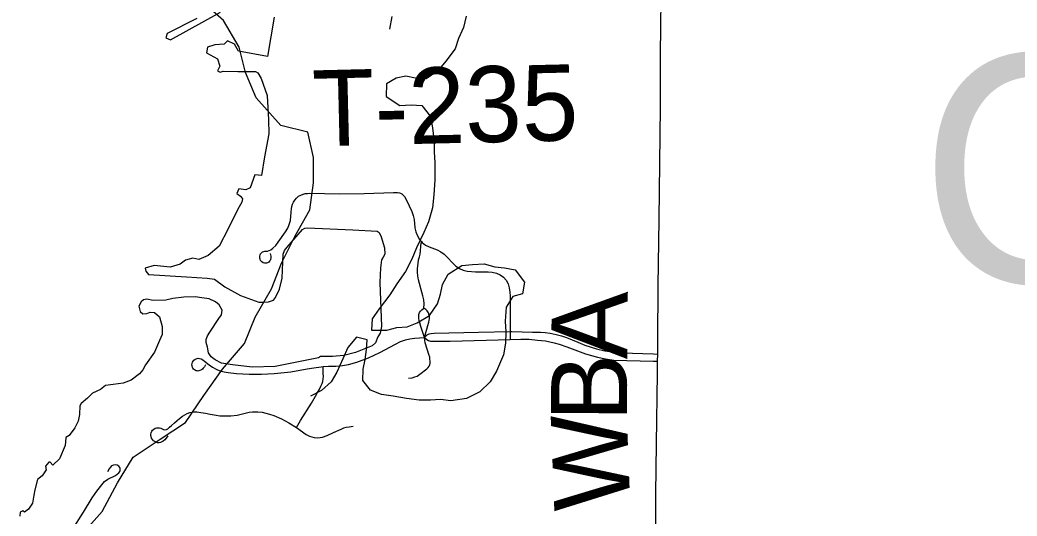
# Model space of a CAD drawing. Extents: x 0 to 34, y 0 to 22.
# Drawn here: x 5.8393 to 6.2117, y 19.8487 to 20.0341 of the extents above; entities that cross this region are included whole.
import ezdxf

# ---------------------------------------------------------------- set-up
doc = ezdxf.new("R2010")
doc.units = 0
for name, color, linetype in [('GM_X_Corporation', 7, 'Continuous'), ('GM_X_County_Road', 7, 'Continuous'), ('GM_X_County_Road_Text', 7, 'Continuous'), ('GM_X_Major_Lake', 7, 'Continuous'), ('GM_X_Minor_River', 7, 'Continuous'), ('GM_X_Township_Road', 7, 'Continuous'), ('GM_X_Township_Road_Text', 7, 'Continuous'), ('GM_X_Township_Text', 7, 'Continuous')]:
    doc.layers.add(name, color=color, linetype=linetype)

msp = doc.modelspace()

# ---------------------------------------------------------------- linework, layer by layer
at = {"layer": 'GM_X_Corporation'}
for points in [[(5.90542, 20.0346), (5.89438, 20.02901), (5.89385, 20.02741), (5.89558, 20.02662), (5.9142, 20.03699)], [(5.90542, 20.0346), (5.89438, 20.02901), (5.89385, 20.02741), (5.89558, 20.02662), (5.9142, 20.03699)], [(5.93428, 20.03513), (5.93176, 20.02037), (5.92092, 20.02243), (5.91952, 20.02502), (5.91689, 20.02624), (5.91566, 20.02502), (5.91214, 20.02476), (5.90941, 20.02396), (5.90901, 20.02183), (5.91307, 20.01957), (5.914, 20.01677), (5.91306, 20.01512), (5.91409, 20.01453), (5.91527, 20.01497), (5.92068, 20.01488), (5.92733, 20.01484), (5.92824, 20.01436), (5.92945, 20.01219), (5.93163, 20.00585), (5.93219, 19.99673), (5.93228, 19.99151), (5.93067, 19.98287), (5.92954, 19.97596), (5.92711, 19.97622), (5.92533, 19.97139), (5.92376, 19.97061), (5.92107, 19.97096), (5.9203, 19.96921), (5.92176, 19.96818), (5.92246, 19.96718), (5.9222, 19.96601), (5.92068, 19.96331), (5.91714, 19.95601), (5.91373, 19.94958), (5.90969, 19.94606), (5.90612, 19.94455), (5.90387, 19.94502), (5.90122, 19.94428), (5.89921, 19.94281), (5.89539, 19.94168), (5.88953, 19.94228), (5.88609, 19.94133), (5.88636, 19.94016), (5.88736, 19.9389), (5.9016, 19.93807), (5.90921, 19.93755), (5.91195, 19.93724), (5.91586, 19.93433), (5.92168, 19.93112), (5.92854, 19.9286), (5.93032, 19.92855), (5.93215, 19.92877), (5.93402, 19.92938), (5.9348, 19.93034), (5.93632, 19.93347), (5.93727, 19.93764), (5.93767, 19.94659), (5.93814, 19.94789), (5.93919, 19.94911), (5.94488, 19.95571), (5.9457, 19.95623), (5.94657, 19.95636), (5.96369, 19.95567), (5.97269, 19.9551), (5.97351, 19.95462), (5.9742, 19.95297), (5.97551, 19.94893), (5.97555, 19.94659), (5.97499, 19.94546), (5.97434, 19.94446), (5.97399, 19.94142), (5.97368, 19.93599), (5.97442, 19.91956), (5.9739, 19.91704), (5.97295, 19.9157), (5.97212, 19.91344), (5.97082, 19.91235), (5.96469, 19.90983), (5.96035, 19.90866), (5.95605, 19.90831), (5.95161, 19.90831), (5.95079, 19.90779), (5.93462, 19.90462), (5.92602, 19.90431), (5.91872, 19.90523), (5.91464, 19.90583), (5.91221, 19.90705), (5.91077, 19.90818), (5.90973, 19.90966), (5.90934, 19.91178), (5.90895, 19.91357), (5.90895, 19.91461), (5.90934, 19.916), (5.91021, 19.91739), (5.91364, 19.92247), (5.91464, 19.92391), (5.91481, 19.9256), (5.91373, 19.92764), (5.91238, 19.92873), (5.90999, 19.92986), (5.90725, 19.93021), (5.90473, 19.9306), (5.90056, 19.93042), (5.89648, 19.92995), (5.89387, 19.92938), (5.88914, 19.92929), (5.88679, 19.92973), (5.88553, 19.92951), (5.88458, 19.92873), (5.88371, 19.92708), (5.88418, 19.92512), (5.88522, 19.9243), (5.88675, 19.92434), (5.88801, 19.92491), (5.88961, 19.92469), (5.89144, 19.92317), (5.89248, 19.91956), (5.89244, 19.91657), (5.89148, 19.91426), (5.88961, 19.90987), (5.88623, 19.90522), (5.88527, 19.90327), (5.88397, 19.90179), (5.88084, 19.8994), (5.87793, 19.8984), (5.8741, 19.89788), (5.87128, 19.89741), (5.86941, 19.89597), (5.8665, 19.89458), (5.86455, 19.89271), (5.86216, 19.8908), (5.86176, 19.88989), (5.86163, 19.88667), (5.86103, 19.88419), (5.85981, 19.88163), (5.85777, 19.87872), (5.85646, 19.87798), (5.85638, 19.87646), (5.8562, 19.87507), (5.85412, 19.87003), (5.85164, 19.86764), (5.85069, 19.86877), (5.85008, 19.86886), (5.84886, 19.8673), (5.84916, 19.8659), (5.8476, 19.86373), (5.84586, 19.86234), (5.84491, 19.85843), (5.84456, 19.85652), (5.84404, 19.85344), (5.84256, 19.85126), (5.841, 19.85018), (5.84039, 19.85061), (5.83939, 19.85013), (5.83935, 19.84857)], [(5.93428, 20.03513), (5.93176, 20.02037), (5.92092, 20.02243), (5.91952, 20.02502), (5.91689, 20.02624), (5.91566, 20.02502), (5.91214, 20.02476), (5.90941, 20.02396), (5.90901, 20.02183), (5.91307, 20.01957), (5.914, 20.01677), (5.91306, 20.01512), (5.91409, 20.01453), (5.91527, 20.01497), (5.92068, 20.01488), (5.92733, 20.01484), (5.92824, 20.01436), (5.92945, 20.01219), (5.93163, 20.00585), (5.93219, 19.99673), (5.93228, 19.99151), (5.93067, 19.98287), (5.92954, 19.97596), (5.92711, 19.97622), (5.92533, 19.97139), (5.92376, 19.97061), (5.92107, 19.97096), (5.9203, 19.96921), (5.92176, 19.96818), (5.92246, 19.96718), (5.9222, 19.96601), (5.92068, 19.96331), (5.91714, 19.95601), (5.91373, 19.94958), (5.90969, 19.94606), (5.90612, 19.94455), (5.90387, 19.94502), (5.90122, 19.94428), (5.89921, 19.94281), (5.89539, 19.94168), (5.88953, 19.94228), (5.88609, 19.94133), (5.88636, 19.94016), (5.88736, 19.9389), (5.9016, 19.93807), (5.90921, 19.93755), (5.91195, 19.93724), (5.91586, 19.93433), (5.92168, 19.93112), (5.92854, 19.9286), (5.93032, 19.92855), (5.93215, 19.92877), (5.93402, 19.92938), (5.9348, 19.93034), (5.93632, 19.93347), (5.93727, 19.93764), (5.93767, 19.94659), (5.93814, 19.94789), (5.93919, 19.94911), (5.94488, 19.95571), (5.9457, 19.95623), (5.94657, 19.95636), (5.96369, 19.95567), (5.97269, 19.9551), (5.97351, 19.95462), (5.9742, 19.95297), (5.97551, 19.94893), (5.97555, 19.94659), (5.97499, 19.94546), (5.97434, 19.94446), (5.97399, 19.94142), (5.97368, 19.93599), (5.97442, 19.91956), (5.9739, 19.91704), (5.97295, 19.9157), (5.97212, 19.91344), (5.97082, 19.91235), (5.96469, 19.90983), (5.96035, 19.90866), (5.95605, 19.90831), (5.95161, 19.90831), (5.95079, 19.90779), (5.93462, 19.90462), (5.92602, 19.90431), (5.91872, 19.90523), (5.91464, 19.90583), (5.91221, 19.90705), (5.91077, 19.90818), (5.90973, 19.90966), (5.90934, 19.91178), (5.90895, 19.91357), (5.90895, 19.91461), (5.90934, 19.916), (5.91021, 19.91739), (5.91364, 19.92247), (5.91464, 19.92391), (5.91481, 19.9256), (5.91373, 19.92764), (5.91238, 19.92873), (5.90999, 19.92986), (5.90725, 19.93021), (5.90473, 19.9306), (5.90056, 19.93042), (5.89648, 19.92995), (5.89387, 19.92938), (5.88914, 19.92929), (5.88679, 19.92973), (5.88553, 19.92951), (5.88458, 19.92873), (5.88371, 19.92708), (5.88418, 19.92512), (5.88522, 19.9243), (5.88675, 19.92434), (5.88801, 19.92491), (5.88961, 19.92469), (5.89144, 19.92317), (5.89248, 19.91956), (5.89244, 19.91657), (5.89148, 19.91426), (5.88961, 19.90987), (5.88623, 19.90522), (5.88527, 19.90327), (5.88397, 19.90179), (5.88084, 19.8994), (5.87793, 19.8984), (5.8741, 19.89788), (5.87128, 19.89741), (5.86941, 19.89597), (5.8665, 19.89458), (5.86455, 19.89271), (5.86216, 19.8908), (5.86176, 19.88989), (5.86163, 19.88667), (5.86103, 19.88419), (5.85981, 19.88163), (5.85777, 19.87872), (5.85646, 19.87798), (5.85638, 19.87646), (5.8562, 19.87507), (5.85412, 19.87003), (5.85164, 19.86764), (5.85069, 19.86877), (5.85008, 19.86886), (5.84886, 19.8673), (5.84916, 19.8659), (5.8476, 19.86373), (5.84586, 19.86234), (5.84491, 19.85843), (5.84456, 19.85652), (5.84404, 19.85344), (5.84256, 19.85126), (5.841, 19.85018), (5.84039, 19.85061), (5.83939, 19.85013), (5.83935, 19.84857)]]:
    msp.add_lwpolyline(points, dxfattribs=at)
at = {"layer": 'GM_X_County_Road'}
for points in [[(6.07746, 19.90651), (6.07751, 19.90922), (6.07761, 19.91447), (6.07765, 19.93467), (6.07802, 19.95953), (6.07849, 20.00148), (6.07856, 20.01856), (6.07873, 20.0341), (6.07876, 20.03932)], [(6.07684, 19.84572), (6.07681, 19.85702), (6.07711, 19.87566), (6.07738, 19.90208), (6.07746, 19.90651)]]:
    msp.add_lwpolyline(points, dxfattribs=at)
at = {"layer": 'GM_X_Major_Lake'}
for points in [[(5.87007, 19.85039), (5.87576, 19.86104), (5.88164, 19.87073), (5.89169, 19.87739), (5.90118, 19.88366), (5.90801, 19.89373), (5.91502, 19.90362), (5.92318, 19.91312), (5.92716, 19.92301), (5.93323, 19.93365), (5.93702, 19.94316), (5.94214, 19.95342), (5.94764, 19.96311), (5.94897, 19.97319), (5.94897, 19.98269), (5.94688, 19.99219), (5.93682, 19.99466), (5.92752, 20.00493), (5.92353, 20.01443), (5.92125, 20.02393), (5.91537, 20.03382), (5.90512, 20.04294)], [(5.86115, 19.84032), (5.87007, 19.85039)]]:
    msp.add_lwpolyline(points, dxfattribs=at)
at = {"layer": 'GM_X_Minor_River'}
for points in [[(6.00593, 20.03549), (6.005, 20.0313), (6.00313, 20.02711), (6.00182, 20.0233), (5.99843, 20.01872), (5.99541, 20.01509), (5.99106, 20.01203), (5.98707, 20.01239), (5.98346, 20.01313), (5.97986, 20.01235), (5.97626, 20.01025), (5.97609, 20.00549), (5.98124, 20.00209), (5.98541, 20.0023), (5.9894, 20.00213), (5.99265, 19.99796), (5.99343, 19.99378), (5.99403, 19.98846), (5.99405, 19.98484), (5.99426, 19.98066), (5.99429, 19.97439), (5.99394, 19.96868), (5.9934, 19.96392), (5.99191, 19.95859), (5.99022, 19.95459), (5.9874, 19.94887), (5.98572, 19.94468), (5.98327, 19.9401), (5.98007, 19.93552), (5.97743, 19.93132), (5.97347, 19.92617), (5.97084, 19.92236), (5.97067, 19.91817), (5.97636, 19.9182), (5.98015, 19.91917), (5.98395, 19.91937), (5.98774, 19.92091), (5.99228, 19.9236), (5.9953, 19.92798), (5.99641, 19.9316), (5.99716, 19.93522), (5.99922, 19.93903), (6.00433, 19.94229), (6.00832, 19.94269), (6.01268, 19.9429), (6.01667, 19.94178), (6.02028, 19.94142), (6.02427, 19.94067), (6.02772, 19.93612), (6.02698, 19.93175), (6.02338, 19.93078), (6.02093, 19.92677), (6.02058, 19.92145), (6.02079, 19.91746), (6.02062, 19.91327), (6.01988, 19.90889), (6.01726, 19.90279), (6.015, 19.89879), (6.01103, 19.89516), (6.00611, 19.89266), (6.00023, 19.89168), (5.99643, 19.89224), (5.99264, 19.89203), (5.98846, 19.89201), (5.98371, 19.89256), (5.97877, 19.89349), (5.9744, 19.89404), (5.97022, 19.89573), (5.96735, 19.89933), (5.96752, 19.90351), (5.96826, 19.90713), (5.96881, 19.91093), (5.96898, 19.91455), (5.96499, 19.91548), (5.96178, 19.91166), (5.9599, 19.90747), (5.95765, 19.90251), (5.95558, 19.89889), (5.95199, 19.89564), (5.94783, 19.89353)], [(5.97748, 20.0306), (5.9784, 20.03536)]]:
    msp.add_lwpolyline(points, dxfattribs=at)
at = {"layer": 'GM_X_Township_Road'}
for points in [[(5.93279, 19.9468), (5.93299, 19.94575), (5.93303, 19.94513), (5.93296, 19.94451), (5.93283, 19.94419), (5.9326, 19.94388), (5.93235, 19.94362), (5.93208, 19.94345), (5.93173, 19.9433), (5.93136, 19.94321), (5.931, 19.94317), (5.93062, 19.94321), (5.93021, 19.94333), (5.92968, 19.94365), (5.92943, 19.9439), (5.92922, 19.94422), (5.92907, 19.94463), (5.92898, 19.945), (5.92895, 19.94537), (5.92894, 19.9458), (5.92904, 19.94628), (5.92921, 19.94664), (5.92953, 19.94708), (5.92992, 19.94738), (5.93041, 19.94756), (5.93081, 19.94762), (5.93139, 19.94766), (5.93183, 19.94773), (5.93241, 19.94794), (5.933, 19.94823), (5.93377, 19.94878), (5.93486, 19.94985), (5.93583, 19.95107), (5.93857, 19.95489), (5.93935, 19.95623), (5.93994, 19.95767), (5.94032, 19.95918), (5.94065, 19.9623), (5.94077, 19.96355), (5.94089, 19.96435), (5.94114, 19.96519), (5.94155, 19.96602), (5.942, 19.96673), (5.94267, 19.96753), (5.94339, 19.96817), (5.94428, 19.96866), (5.94506, 19.96899), (5.94586, 19.9692), (5.94668, 19.96928), (5.94757, 19.96932), (5.95851, 19.96905), (5.96788, 19.96919), (5.97884, 19.9696), (5.98035, 19.96958), (5.98107, 19.9695), (5.98143, 19.96939), (5.98191, 19.96913), (5.98238, 19.96873), (5.9829, 19.96811), (5.98366, 19.96673), (5.98563, 19.96244), (5.98619, 19.96099), (5.98654, 19.95948), (5.98686, 19.95637), (5.98719, 19.95486), (5.98776, 19.95341), (5.98857, 19.95207), (5.98924, 19.95128)], [(5.99018, 19.92642), (5.99027, 19.92796), (5.99012, 19.92948), (5.98984, 19.93099), (5.98815, 19.93694), (5.98791, 19.93847), (5.98784, 19.93973), (5.98784, 19.94116), (5.98803, 19.94311), (5.98823, 19.94438), (5.98859, 19.94557), (5.98879, 19.94649), (5.98895, 19.94768), (5.98906, 19.94967), (5.98924, 19.95128)], [(5.98924, 19.95128), (5.98958, 19.95088), (5.99078, 19.94993), (5.99218, 19.94924), (5.99512, 19.94818), (5.99649, 19.94747), (5.99773, 19.94654), (5.99886, 19.94545), (6.00099, 19.94315), (6.00215, 19.94211), (6.00344, 19.94125), (6.00485, 19.94063), (6.00635, 19.94024), (6.00791, 19.94004), (6.00947, 19.93996), (6.01418, 19.93993), (6.01574, 19.93979), (6.01725, 19.93945), (6.01868, 19.93884), (6.01994, 19.93794), (6.02095, 19.93679), (6.02167, 19.93542), (6.02208, 19.93393), (6.0223, 19.93237), (6.02238, 19.9308), (6.02243, 19.91764)], [(5.99048, 19.91542), (5.98906, 19.91957), (5.98863, 19.92085), (5.98844, 19.92179), (5.98833, 19.92256), (5.9883, 19.92332), (5.98833, 19.92405), (5.98851, 19.92472), (5.98888, 19.92529), (5.98939, 19.9258), (5.99018, 19.92642)], [(5.99048, 19.91542), (5.99128, 19.91855), (5.99168, 19.91987), (5.99205, 19.92117), (5.99219, 19.92187), (5.99227, 19.92241), (5.99228, 19.92284), (5.99212, 19.9238), (5.99187, 19.92463), (5.99146, 19.92532), (5.99092, 19.92591), (5.99018, 19.92642)], [(5.99048, 19.91542), (5.99139, 19.91641), (5.99212, 19.91681), (5.99292, 19.91695), (5.99398, 19.91705), (6.01057, 19.91746), (6.02243, 19.91764)], [(6.02243, 19.91764), (6.023, 19.91766), (6.03077, 19.91745), (6.03372, 19.91736), (6.03544, 19.91725), (6.0374, 19.917), (6.03955, 19.91652), (6.04152, 19.91598), (6.04341, 19.9154), (6.04767, 19.91365), (6.05026, 19.9126), (6.0547, 19.91117), (6.05771, 19.91043), (6.06088, 19.91001), (6.06408, 19.90973), (6.07592, 19.90928), (6.07751, 19.90922)], [(6.02243, 19.91764), (6.02244, 19.9155), (6.02245, 19.91469)], [(5.95254, 19.90452), (5.9546, 19.90466), (5.95736, 19.90474), (5.95974, 19.90497), (5.9621, 19.90537), (5.9651, 19.90621), (5.96949, 19.90784), (5.97375, 19.90978), (5.97963, 19.91291), (5.98146, 19.91385), (5.98329, 19.91453), (5.98491, 19.91495), (5.98663, 19.91521), (5.99048, 19.91542)], [(5.98449, 19.90019), (5.98577, 19.90037), (5.98684, 19.90066), (5.98763, 19.90098), (5.98873, 19.90168), (5.99124, 19.90373), (5.99177, 19.90424), (5.99215, 19.90474), (5.99235, 19.90523), (5.99252, 19.90581), (5.99255, 19.90651), (5.99247, 19.90736), (5.99235, 19.90806), (5.99209, 19.90908), (5.99159, 19.91062), (5.99113, 19.91184), (5.99086, 19.91263), (5.99069, 19.91339), (5.99048, 19.91542)], [(5.99048, 19.91542), (5.99128, 19.9147), (5.9919, 19.91426), (5.9926, 19.91406), (6, 19.91406), (6.02245, 19.91469)], [(6.02245, 19.91469), (6.02645, 19.9148), (6.02956, 19.91475), (6.03265, 19.91447), (6.03562, 19.91412), (6.03879, 19.91347), (6.04075, 19.91292), (6.04359, 19.91186), (6.05056, 19.90931), (6.05503, 19.908), (6.05807, 19.90737), (6.06116, 19.90698), (6.07581, 19.90655), (6.07746, 19.90651)], [(5.9086, 19.90518), (5.90842, 19.90474), (5.90823, 19.90441), (5.9078, 19.9039), (5.90748, 19.90356), (5.9071, 19.9033), (5.90657, 19.90302), (5.90621, 19.90292), (5.90589, 19.90288), (5.90558, 19.9029), (5.90516, 19.90298), (5.90485, 19.90309), (5.90422, 19.90354), (5.90395, 19.90389), (5.90375, 19.90423), (5.9036, 19.90479), (5.90358, 19.90524), (5.90363, 19.90572), (5.90382, 19.90621), (5.90401, 19.90655), (5.90425, 19.90688), (5.90463, 19.90723), (5.90512, 19.90749), (5.90553, 19.9076), (5.90595, 19.90765), (5.90643, 19.90761), (5.90703, 19.90742), (5.90759, 19.90706), (5.90821, 19.90655), (5.90995, 19.90516), (5.91127, 19.90432), (5.91266, 19.90362), (5.91404, 19.90298), (5.91561, 19.90262), (5.91715, 19.90237), (5.92024, 19.90193), (5.92491, 19.90164), (5.92959, 19.90167), (5.93426, 19.90193), (5.94046, 19.90263), (5.94663, 19.90372), (5.94912, 19.90413), (5.95184, 19.90447), (5.95254, 19.90452)], [(5.94258, 19.88174), (5.94417, 19.88435), (5.94817, 19.89091), (5.94975, 19.89354), (5.95052, 19.89487), (5.95105, 19.89582), (5.95173, 19.89718), (5.95215, 19.8982), (5.95241, 19.89899), (5.95264, 19.89998), (5.95268, 19.90092), (5.95264, 19.90182), (5.95254, 19.90452)], [(5.89455, 19.87864), (5.89393, 19.87772), (5.89345, 19.87718), (5.89281, 19.87664), (5.89233, 19.87635), (5.89179, 19.87616), (5.89133, 19.87609), (5.89073, 19.87609), (5.89023, 19.87624), (5.88969, 19.87649), (5.88922, 19.87683), (5.88883, 19.8773), (5.88853, 19.8778), (5.88833, 19.87838), (5.88824, 19.87879), (5.88824, 19.87927), (5.88834, 19.8798), (5.88856, 19.88035), (5.88884, 19.88073), (5.88931, 19.88116), (5.88989, 19.88146), (5.89038, 19.88161), (5.89091, 19.8817), (5.8914, 19.88166), (5.89196, 19.8815), (5.89241, 19.88128), (5.89296, 19.88101), (5.89335, 19.88094), (5.89405, 19.88105), (5.89459, 19.88133), (5.89517, 19.88185), (5.89592, 19.88246), (5.8971, 19.88353), (5.89801, 19.88433), (5.89895, 19.88516), (5.90009, 19.88599), (5.90092, 19.88652), (5.90182, 19.88701), (5.90284, 19.88735), (5.90352, 19.88754), (5.90435, 19.88761), (5.90541, 19.88761), (5.90685, 19.88742), (5.90862, 19.88709), (5.9104, 19.88678), (5.91263, 19.88633), (5.91403, 19.88618), (5.91576, 19.8861), (5.91807, 19.88614), (5.92042, 19.88643), (5.92498, 19.88747), (5.92616, 19.88758), (5.92714, 19.88762), (5.92816, 19.88762), (5.92974, 19.88747), (5.93114, 19.88713), (5.93258, 19.88675), (5.9342, 19.88622), (5.93704, 19.88497), (5.9397, 19.88355), (5.94258, 19.88174)], [(5.94258, 19.88174), (5.94621, 19.8792), (5.9475, 19.87859), (5.94837, 19.87825), (5.94924, 19.87807), (5.95041, 19.87795), (5.95143, 19.87806), (5.95238, 19.87821), (5.95404, 19.87874), (5.95643, 19.87987), (5.95927, 19.88119), (5.96027, 19.88161), (5.96118, 19.88192), (5.96227, 19.88208), (5.96382, 19.88229)], [(5.85899, 19.84362), (5.86309, 19.85018), (5.86631, 19.85547), (5.86806, 19.85801), (5.86997, 19.8604), (5.87098, 19.86154), (5.87216, 19.86247), (5.875, 19.86382), (5.87565, 19.86431), (5.87623, 19.86479), (5.87662, 19.86538), (5.87676, 19.86574), (5.87681, 19.86606), (5.87674, 19.86643), (5.8766, 19.86678), (5.87626, 19.86731), (5.87567, 19.86772), (5.87507, 19.86787), (5.87424, 19.8677), (5.87352, 19.86739), (5.87298, 19.86688), (5.87263, 19.86637), (5.872, 19.86523)]]:
    msp.add_lwpolyline(points, dxfattribs=at)

# ---------------------------------------------------------------- texts
at = {"layer": 'GM_X_County_Road_Text'}
for s, rotation, p in [('A', 89.5337, (6.06615, 19.90727)), ('B', 89.7346, (6.06604, 19.88396)), ('W', 92.2125, (6.06731, 19.85139))]:
    msp.add_text(s, height=0.02841, rotation=rotation, dxfattribs=at).set_placement(p)
at = {"layer": 'GM_X_Township_Road_Text'}
msp.add_text('T-235', height=0.028409, rotation=1.3766, dxfattribs=at).set_placement((5.94889, 19.98681))
at = {"layer": 'GM_X_Township_Text'}
msp.add_text('CATAWBA', height=0.085227, rotation=0, dxfattribs=at).set_placement((6.17539, 19.93592))

doc.saveas('drawing.dxf')
